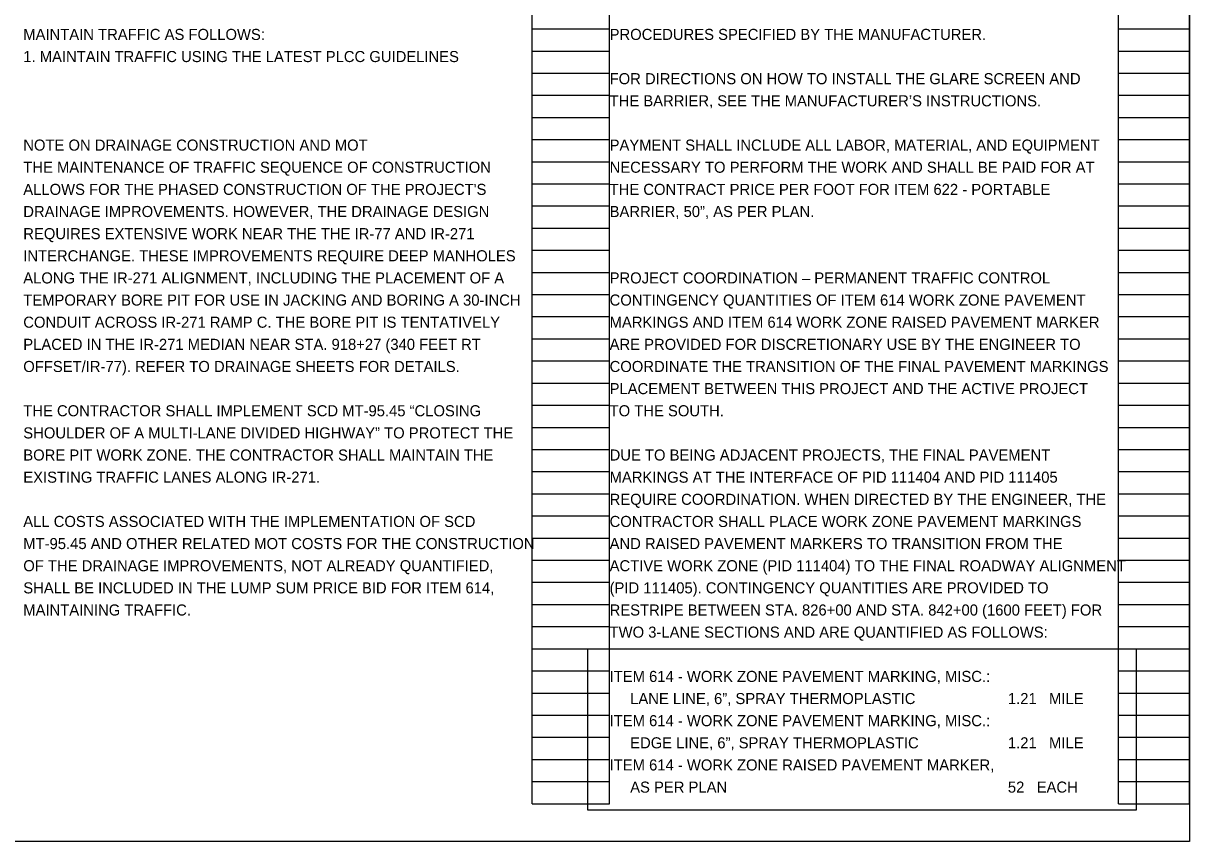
# Model space of a CAD drawing. Extents: x 1820207 to 1820557, y 740216 to 740315.
# Drawn here: x 1820277.13 to 1820291.89, y 740254.74 to 740265.09 of the extents above; entities that cross this region are included whole.
import ezdxf

# ---------------------------------------------------------------- set-up
doc = ezdxf.new("R2010")
doc.units = 0
for name, color, linetype in [('SC_Scratch1', 7, 'Continuous'), ('SC_Scratch2', 7, 'Continuous'), ('SC_Shading1', 7, 'Continuous'), ('SH_Text', 7, 'Continuous')]:
    doc.layers.add(name, color=color, linetype=linetype)

msp = doc.modelspace()

# ---------------------------------------------------------------- linework, layer by layer
at = {"layer": 'SC_Scratch1'}
for p, q in [((1820283.57, 740255.222), (1820283.57, 740275.382)), ((1820284.55, 740255.222), (1820284.55, 740275.382)), ((1820290.99, 740255.222), (1820290.99, 740275.382)), ((1820291.89, 740255.222), (1820291.89, 740275.382)), ((1820283.57, 740265.022), (1820284.55, 740265.022)), ((1820290.99, 740265.022), (1820291.89, 740265.022)), ((1820283.57, 740264.742), (1820284.55, 740264.742)), ((1820290.99, 740264.742), (1820291.89, 740264.742)), ((1820283.57, 740264.462), (1820284.55, 740264.462)), ((1820290.99, 740264.462), (1820291.89, 740264.462)), ((1820283.57, 740264.182), (1820284.55, 740264.182)), ((1820290.99, 740264.182), (1820291.89, 740264.182)), ((1820283.57, 740263.902), (1820284.55, 740263.902)), ((1820290.99, 740263.902), (1820291.89, 740263.902)), ((1820283.57, 740263.622), (1820284.55, 740263.622)), ((1820290.99, 740263.622), (1820291.89, 740263.622)), ((1820283.57, 740263.342), (1820284.55, 740263.342)), ((1820290.99, 740263.342), (1820291.89, 740263.342)), ((1820283.57, 740263.062), (1820284.55, 740263.062)), ((1820290.99, 740263.062), (1820291.89, 740263.062)), ((1820283.57, 740262.782), (1820284.55, 740262.782)), ((1820290.99, 740262.782), (1820291.89, 740262.782)), ((1820283.57, 740262.502), (1820284.55, 740262.502)), ((1820290.99, 740262.502), (1820291.89, 740262.502)), ((1820283.57, 740262.222), (1820284.55, 740262.222)), ((1820290.99, 740262.222), (1820291.89, 740262.222)), ((1820283.57, 740261.942), (1820284.55, 740261.942)), ((1820290.99, 740261.942), (1820291.89, 740261.942)), ((1820283.57, 740261.662), (1820284.55, 740261.662)), ((1820290.99, 740261.662), (1820291.89, 740261.662)), ((1820283.57, 740261.382), (1820284.55, 740261.382)), ((1820290.99, 740261.382), (1820291.89, 740261.382)), ((1820283.57, 740261.102), (1820284.55, 740261.102)), ((1820290.99, 740261.102), (1820291.89, 740261.102)), ((1820283.57, 740260.822), (1820284.55, 740260.822)), ((1820290.99, 740260.822), (1820291.89, 740260.822)), ((1820283.57, 740260.542), (1820284.55, 740260.542)), ((1820290.99, 740260.542), (1820291.89, 740260.542)), ((1820283.57, 740260.262), (1820284.55, 740260.262)), ((1820290.99, 740260.262), (1820291.89, 740260.262)), ((1820283.57, 740259.982), (1820284.55, 740259.982)), ((1820290.99, 740259.982), (1820291.89, 740259.982)), ((1820283.57, 740259.702), (1820284.55, 740259.702)), ((1820290.99, 740259.702), (1820291.89, 740259.702)), ((1820283.57, 740259.422), (1820284.55, 740259.422)), ((1820290.99, 740259.422), (1820291.89, 740259.422)), ((1820283.57, 740259.142), (1820284.55, 740259.142)), ((1820290.99, 740259.142), (1820291.89, 740259.142)), ((1820283.57, 740258.862), (1820284.55, 740258.862)), ((1820290.99, 740258.862), (1820291.89, 740258.862)), ((1820283.57, 740258.582), (1820284.55, 740258.582)), ((1820290.99, 740258.582), (1820291.89, 740258.582)), ((1820283.57, 740258.302), (1820284.55, 740258.302)), ((1820290.99, 740258.302), (1820291.89, 740258.302)), ((1820283.57, 740258.022), (1820284.55, 740258.022)), ((1820290.99, 740258.022), (1820291.89, 740258.022)), ((1820283.57, 740257.742), (1820284.55, 740257.742)), ((1820290.99, 740257.742), (1820291.89, 740257.742)), ((1820283.57, 740257.462), (1820284.55, 740257.462)), ((1820290.99, 740257.462), (1820291.89, 740257.462)), ((1820283.57, 740257.182), (1820284.55, 740257.182)), ((1820290.99, 740257.182), (1820291.89, 740257.182)), ((1820283.57, 740256.902), (1820284.55, 740256.902)), ((1820290.99, 740256.902), (1820291.89, 740256.902)), ((1820283.57, 740256.622), (1820284.55, 740256.622)), ((1820290.99, 740256.622), (1820291.89, 740256.622)), ((1820283.57, 740256.342), (1820284.55, 740256.342)), ((1820290.99, 740256.342), (1820291.89, 740256.342)), ((1820283.57, 740256.062), (1820284.55, 740256.062)), ((1820290.99, 740256.062), (1820291.89, 740256.062)), ((1820283.57, 740255.782), (1820284.55, 740255.782)), ((1820290.99, 740255.782), (1820291.89, 740255.782)), ((1820283.57, 740255.502), (1820284.55, 740255.502)), ((1820290.99, 740255.502), (1820291.89, 740255.502)), ((1820283.57, 740255.222), (1820284.55, 740255.222)), ((1820290.99, 740255.222), (1820291.89, 740255.222))]:
    msp.add_line(p, q, dxfattribs=at)
at = {"layer": 'SC_Scratch2'}
msp.add_lwpolyline([(1820261.39, 740275.742), (1820291.89, 740275.742), (1820291.89, 740254.742), (1820261.39, 740254.742)], close=True, dxfattribs=at)
at = {"layer": 'SC_Shading1'}
msp.add_lwpolyline([(1820284.275, 740257.182), (1820291.214, 740257.182), (1820291.214, 740255.139), (1820284.275, 740255.139)], close=True, dxfattribs=at)

# ---------------------------------------------------------------- texts
at = {"layer": 'SH_Text'}
for s, p in [('MAINTAIN TRAFFIC AS FOLLOWS:', (1820277.13, 740264.882)), ('1. MAINTAIN TRAFFIC USING THE LATEST PLCC GUIDELINES', (1820277.13, 740264.602))]:
    msp.add_text(s, height=0.14, rotation=360, dxfattribs=at).set_placement(p)
for s, p in [('PROCEDURES SPECIFIED BY THE MANUFACTURER.', (1820284.55, 740264.882)), ('FOR DIRECTIONS ON HOW TO INSTALL THE GLARE SCREEN AND ', (1820284.55, 740264.322)), ('THE BARRIER, SEE THE MANUFACTURER’S INSTRUCTIONS.', (1820284.55, 740264.042)), ('NOTE ON DRAINAGE CONSTRUCTION AND MOT', (1820277.13, 740263.482)), ('PAYMENT SHALL INCLUDE ALL LABOR, MATERIAL, AND EQUIPMENT ', (1820284.55, 740263.482)), ('THE MAINTENANCE OF TRAFFIC SEQUENCE OF CONSTRUCTION ', (1820277.13, 740263.202)), ('NECESSARY TO PERFORM THE WORK AND SHALL BE PAID FOR AT ', (1820284.55, 740263.202)), ("ALLOWS FOR THE PHASED CONSTRUCTION OF THE PROJECT'S ", (1820277.13, 740262.922)), ('THE CONTRACT PRICE PER FOOT FOR ITEM 622 - PORTABLE ', (1820284.55, 740262.922)), ('DRAINAGE IMPROVEMENTS. HOWEVER, THE DRAINAGE DESIGN ', (1820277.13, 740262.642)), ('BARRIER, 50”, AS PER PLAN.', (1820284.55, 740262.642)), ('REQUIRES EXTENSIVE WORK NEAR THE THE IR-77 AND IR-271 ', (1820277.13, 740262.362)), ('INTERCHANGE. THESE IMPROVEMENTS REQUIRE DEEP MANHOLES ', (1820277.13, 740262.082)), ('ALONG THE IR-271 ALIGNMENT, INCLUDING THE PLACEMENT OF A ', (1820277.13, 740261.802)), ('PROJECT COORDINATION – PERMANENT TRAFFIC CONTROL', (1820284.55, 740261.802)), ('TEMPORARY BORE PIT FOR USE IN JACKING AND BORING A 30-INCH ', (1820277.13, 740261.522)), ('CONTINGENCY QUANTITIES OF ITEM 614 WORK ZONE PAVEMENT ', (1820284.55, 740261.522)), ('CONDUIT ACROSS IR-271 RAMP C. THE BORE PIT IS TENTATIVELY ', (1820277.13, 740261.242)), ('MARKINGS AND ITEM 614 WORK ZONE RAISED PAVEMENT MARKER ', (1820284.55, 740261.242)), ('PLACED IN THE IR-271 MEDIAN NEAR STA. 918+27 (340 FEET RT ', (1820277.13, 740260.962)), ('ARE PROVIDED FOR DISCRETIONARY USE BY THE ENGINEER TO ', (1820284.55, 740260.962)), ('OFFSET/IR-77). REFER TO DRAINAGE SHEETS FOR DETAILS.', (1820277.13, 740260.682)), ('COORDINATE THE TRANSITION OF THE FINAL PAVEMENT MARKINGS ', (1820284.55, 740260.682)), ('PLACEMENT BETWEEN THIS PROJECT AND THE ACTIVE PROJECT ', (1820284.55, 740260.402)), ('THE CONTRACTOR SHALL IMPLEMENT SCD MT-95.45 “CLOSING ', (1820277.13, 740260.122)), ('TO THE SOUTH.', (1820284.55, 740260.122)), ('SHOULDER OF A MULTI-LANE DIVIDED HIGHWAY” TO PROTECT THE', (1820277.13, 740259.842)), ('BORE PIT WORK ZONE. THE CONTRACTOR SHALL MAINTAIN THE ', (1820277.13, 740259.562)), ('DUE TO BEING ADJACENT PROJECTS, THE FINAL PAVEMENT ', (1820284.55, 740259.562)), ('EXISTING TRAFFIC LANES ALONG IR-271. ', (1820277.13, 740259.282)), ('MARKINGS AT THE INTERFACE OF PID 111404 AND PID 111405 ', (1820284.55, 740259.282)), ('REQUIRE COORDINATION. WHEN DIRECTED BY THE ENGINEER, THE ', (1820284.55, 740259.002)), ('ALL COSTS ASSOCIATED WITH THE IMPLEMENTATION OF SCD ', (1820277.13, 740258.722)), ('CONTRACTOR SHALL PLACE WORK ZONE PAVEMENT MARKINGS ', (1820284.55, 740258.722)), ('MT-95.45 AND OTHER RELATED MOT COSTS FOR THE CONSTRUCTION ', (1820277.13, 740258.442)), ('AND RAISED PAVEMENT MARKERS TO TRANSITION FROM THE ', (1820284.55, 740258.442)), ('OF THE DRAINAGE IMPROVEMENTS, NOT ALREADY QUANTIFIED, ', (1820277.13, 740258.162)), ('ACTIVE WORK ZONE (PID 111404) TO THE FINAL ROADWAY ALIGNMENT ', (1820284.55, 740258.162)), ('SHALL BE INCLUDED IN THE LUMP SUM PRICE BID FOR ITEM 614, ', (1820277.13, 740257.882)), ('(PID 111405). CONTINGENCY QUANTITIES ARE PROVIDED TO ', (1820284.55, 740257.882)), ('MAINTAINING TRAFFIC.', (1820277.13, 740257.602)), ('RESTRIPE BETWEEN STA. 826+00 AND STA. 842+00 (1600 FEET) FOR ', (1820284.55, 740257.602)), ('TWO 3-LANE SECTIONS AND ARE QUANTIFIED AS FOLLOWS:', (1820284.55, 740257.322)), ('ITEM 614 - WORK ZONE PAVEMENT MARKING, MISC.: ', (1820284.55, 740256.762)), ('     LANE LINE, 6”, SPRAY THERMOPLASTIC', (1820284.55, 740256.482)), ('1.21   MILE', (1820289.59, 740256.482)), ('ITEM 614 - WORK ZONE PAVEMENT MARKING, MISC.: ', (1820284.55, 740256.202)), ('     EDGE LINE, 6”, SPRAY THERMOPLASTIC', (1820284.55, 740255.922)), ('1.21   MILE', (1820289.59, 740255.922)), ('ITEM 614 - WORK ZONE RAISED PAVEMENT MARKER, ', (1820284.55, 740255.642)), ('     AS PER PLAN', (1820284.55, 740255.362)), ('52   EACH', (1820289.59, 740255.362))]:
    msp.add_text(s, height=0.14, dxfattribs=at).set_placement(p)

doc.saveas('drawing.dxf')
